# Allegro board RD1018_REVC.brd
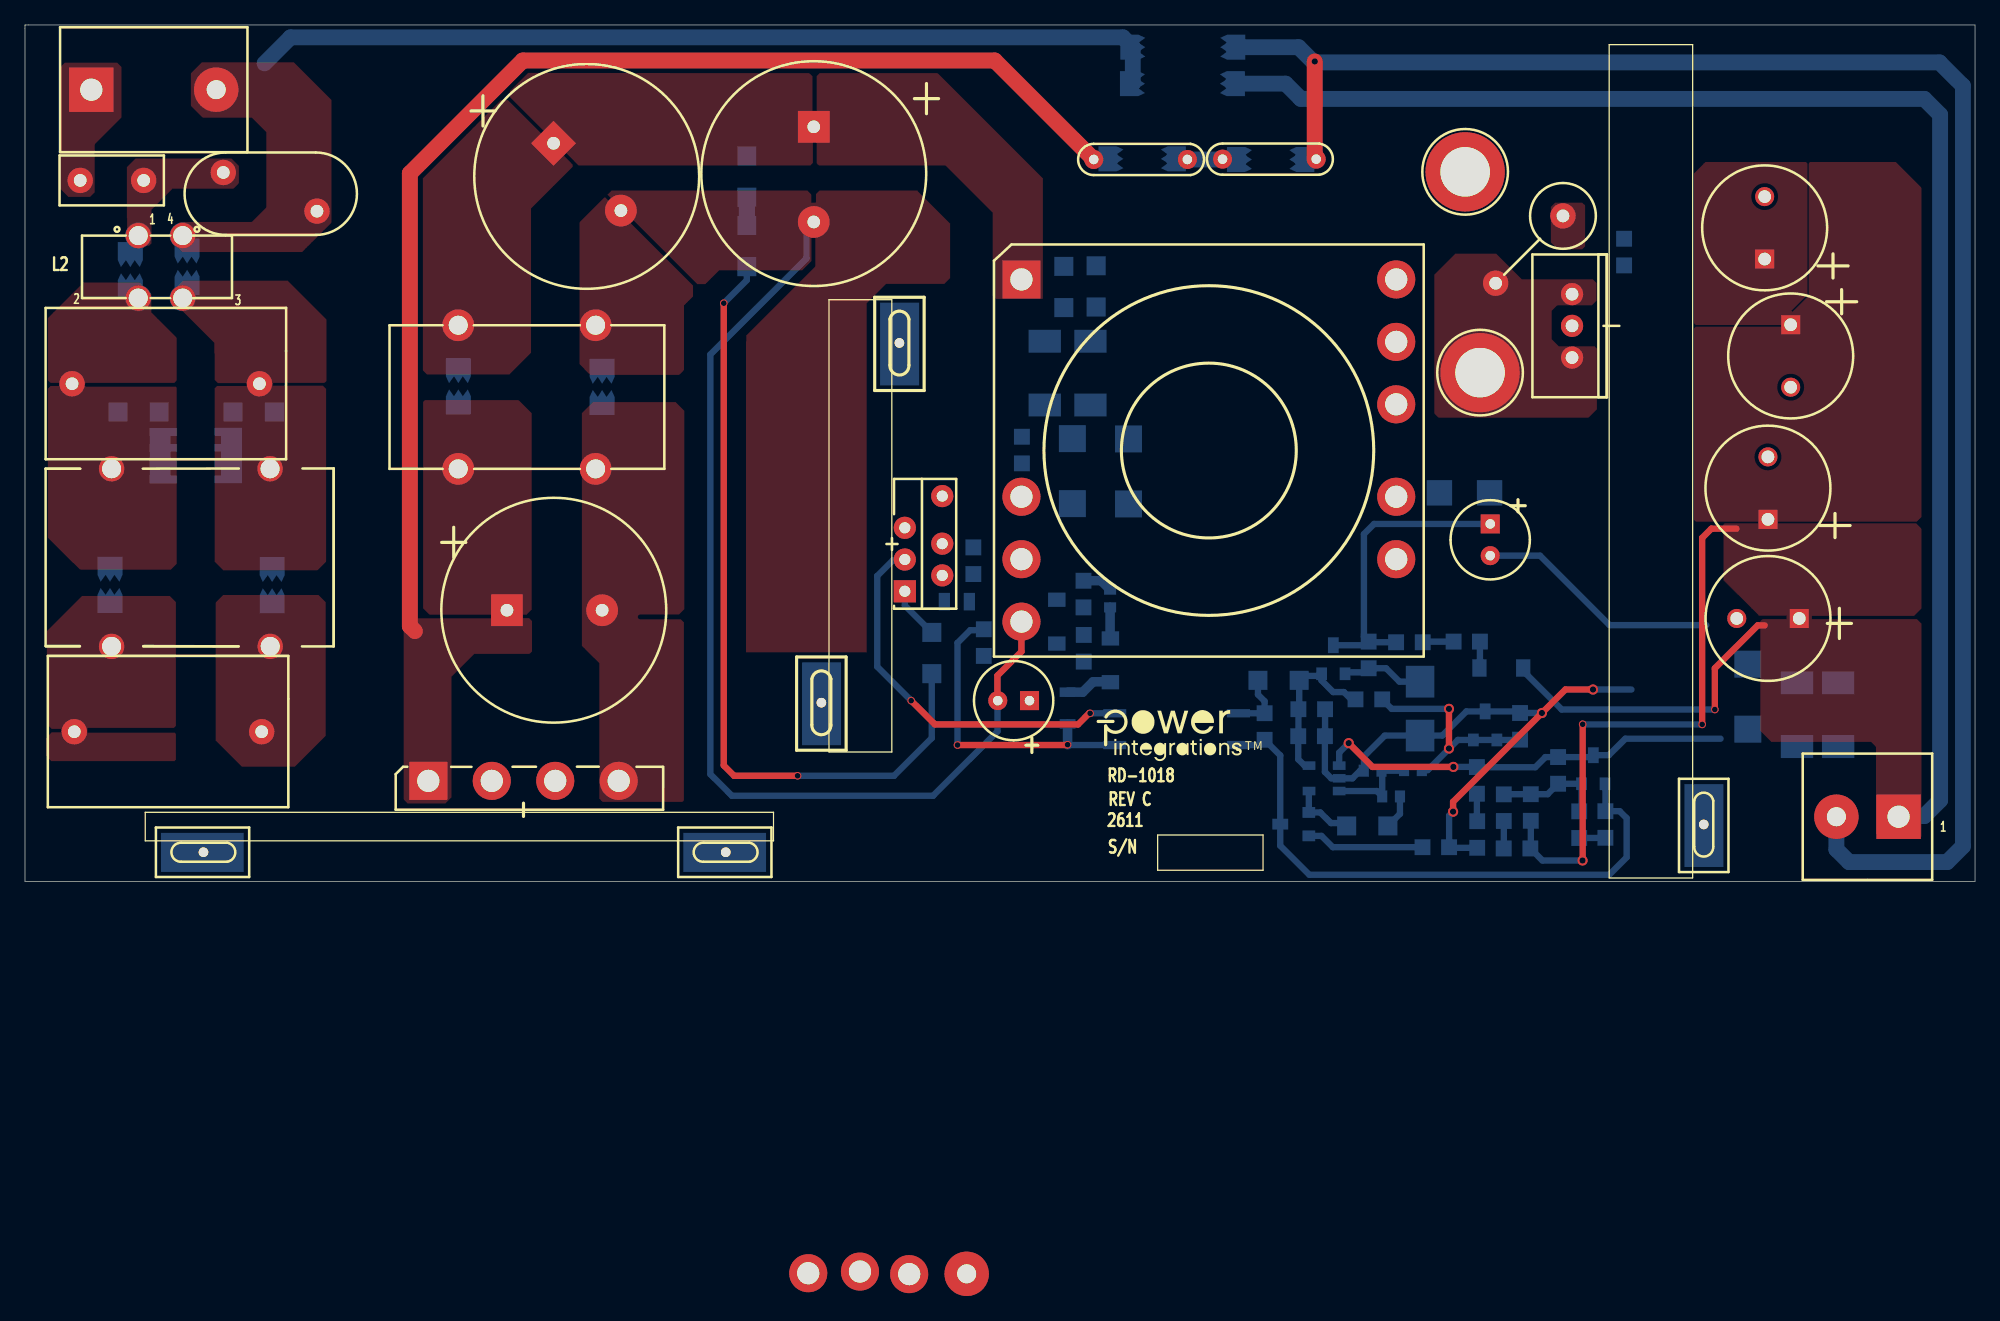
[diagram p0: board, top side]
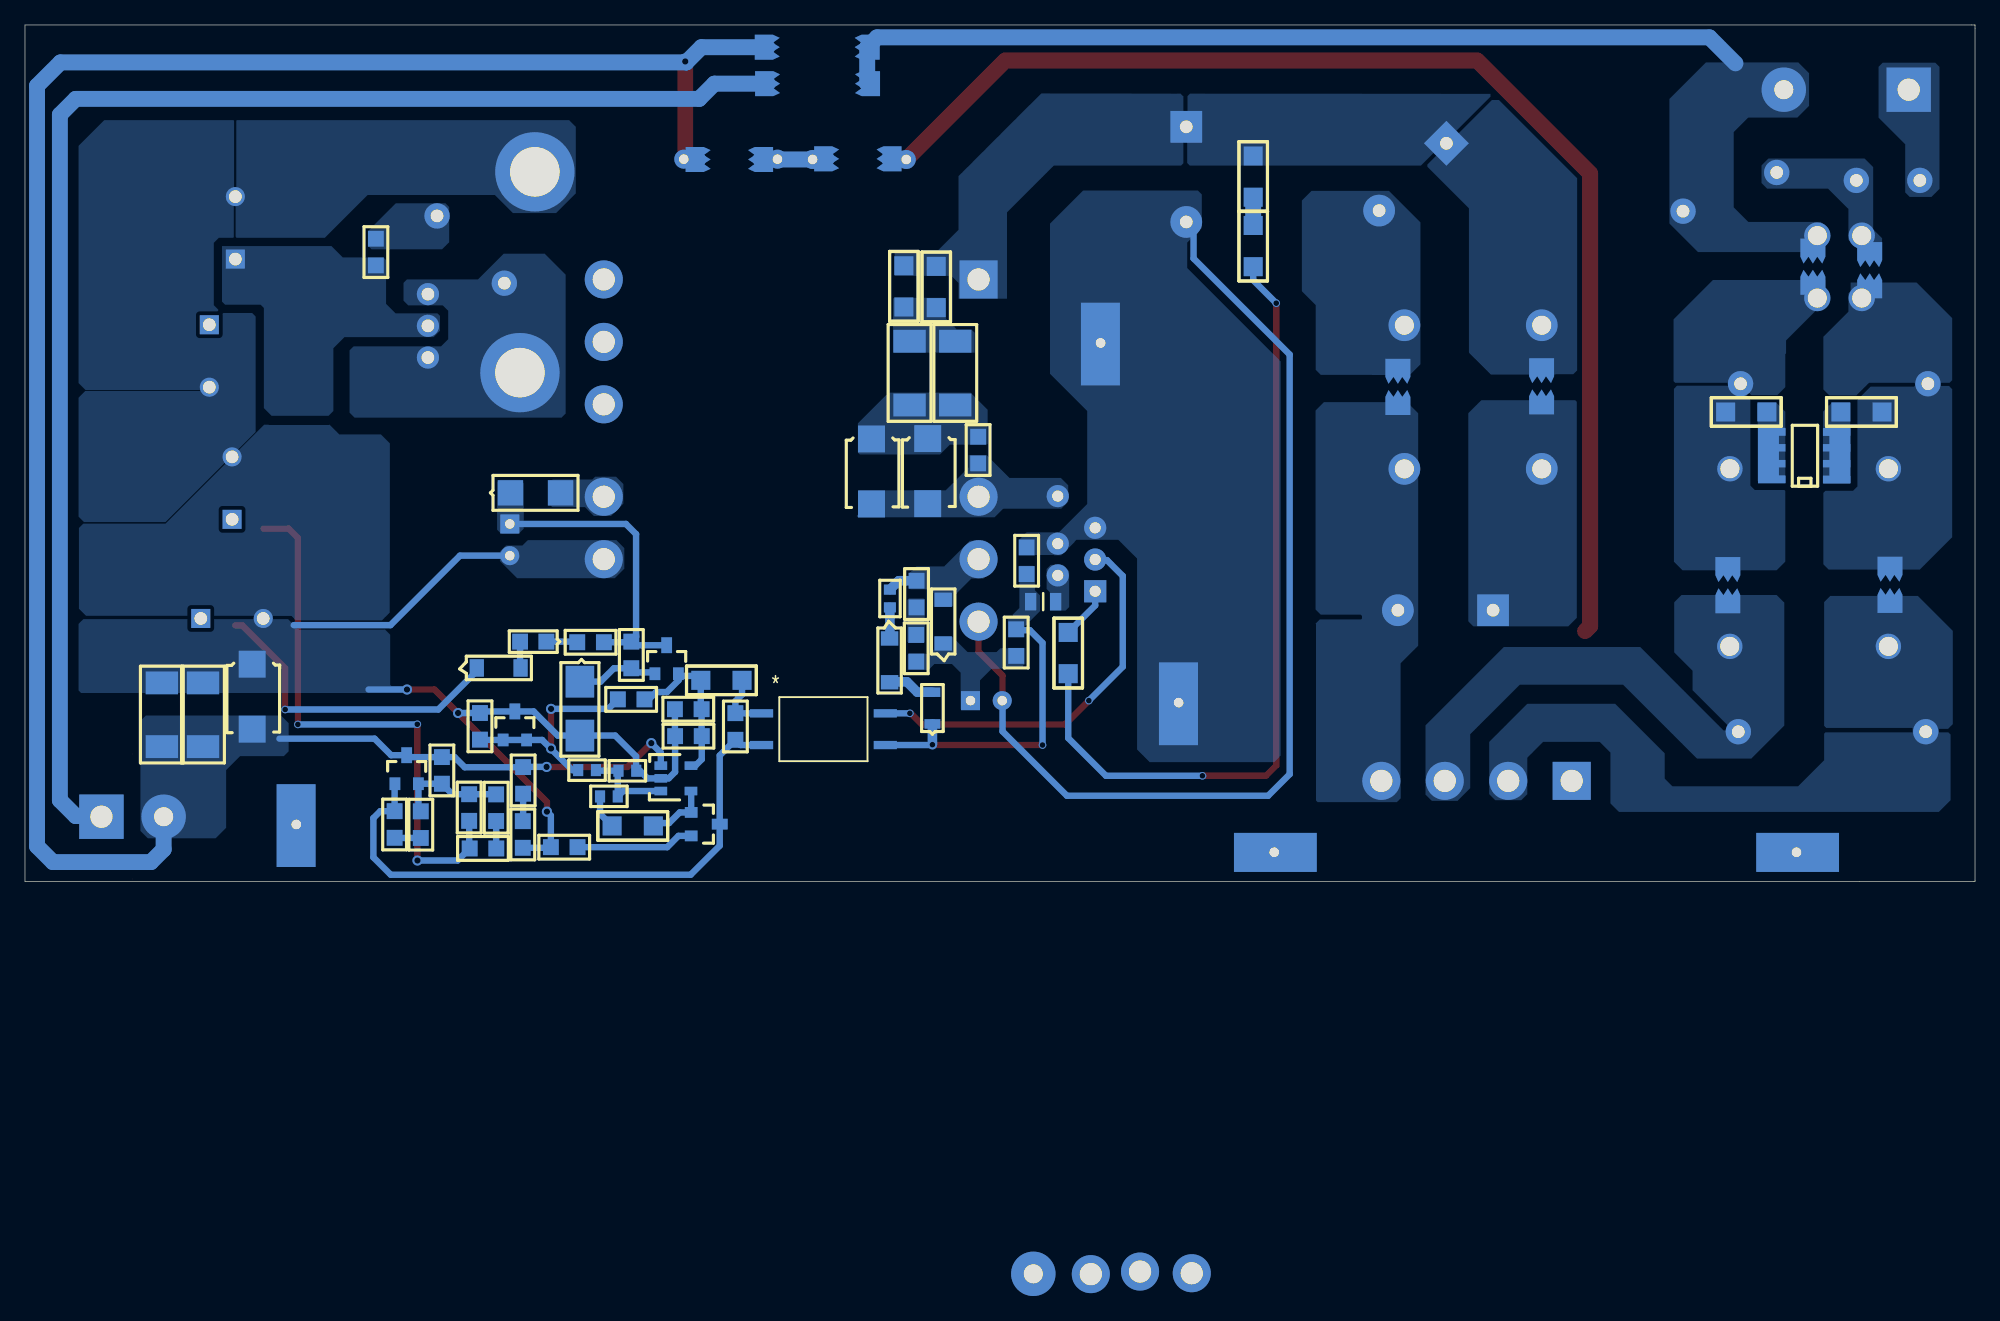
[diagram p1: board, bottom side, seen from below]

Outline 156.11 x 68.58 mm; copper layers: TOP, BOTTOM. Coordinates in mm from the lower left corner of the outline.
Outline path: 0,68.58 156.11,68.58 156.11,0 0,0 0,68.58

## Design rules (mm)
constraint set DEFAULT: min track width 0.508

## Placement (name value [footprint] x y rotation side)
BR1  GBU10KL-BP  [PIDAXBRIDGEGBU8]  32.29 8.05 0 top
C1  680 nF  [PINPXCAPRAD710X430720040]  18.95 11.99 180 top
C2  680 nF  [PINPXCAPRAD710X430720040]  18.77 39.85 180 top
C3  150 uF  [PIPOLCAPCLYD18LS7P5H37D40V]  38.58 21.72 0 top
C4  150 uF  [PIPOLCAPCLYD18LS7P5H37D40V]  42.32 59.11 315 top
C5  150 uF  [PIPOLCAPCLYD18LS7P5H37D40V]  63.14 60.43 270 top
C7  0.47 uF  [PISMC0805]  75.92 24.61 90 bottom
C8  47 pF  [PISMC0805]  79.81 35.61 270 bottom
C9  4700 pF  [PISMC1206]  83.16 49.25 270 bottom
C10  330 pF  [PISMC0805]  84.73 24.08 270 bottom
C11  22 uF  [PIPOLCAPCYLD250LS100030]  80.42 14.48 180 top
C12  100 nF  [PISMC0805]  119.68 11.35 90 bottom
C13  47 uF  [PIPOLCAPCYLD250LS100030]  117.3 28.63 270 top
C14  470 pF  [PISMC0805]  128.02 51.46 270 bottom
C15  10 nF  [PISMC0805]  116.23 7.02 90 bottom
C16  220 nF  [PISMC0603]  108.65 6.81 0 bottom
C17  220 uF  [PIPOLCAPCLYD10MM040]  141.35 44.58 270 top
C18  100 nF  [PISMC0805]  104.06 11.63 180 bottom
C19  100 nF  [PISMC0805]  101.94 13.79 0 bottom
C20  220 uF  [PIPOLCAPCLYD10MM040]  139.27 49.83 90 top
C21  220 uF  [PIPOLCAPCLYD10MM040]  139.53 28.99 90 top
C22  120 uF  [PIPOLCAPCLYD10MM040]  142.04 21.06 180 top
C23  10 nF  [PISMC0805]  126.52 5.63 270 bottom
C24  10 nF  [PISMC0805]  118.39 4.84 90 bottom
CY1  4700 pF  [PINPCAPRAD10DX7P5MM]  89.31 57.81 0 top
CY2  4700 pF  [PINPCAPRAD10DX7P5MM]  99.62 57.84 0 top
D1  BAV21WS-7-F  [PISMSOD323]  83.46 12.61 90 bottom
D2  S2M  [PISMSMB]  83.85 35.46 270 bottom
D3  S2M  [PISMSMB]  88.34 35.43 270 bottom
D4  S1MLHRVG  [PI_SM_SOD-123_12]  82.6 19.05 90 bottom
D5  US1D  [PISMDSMA]  117.25 31.11 180 bottom
D6  STTH2003CT  [PIDVTO2203]  123.85 47.16 270 top
D7  1N4148WS  [PISMDSOD323]  114.37 19.2 0 bottom
D9  S1AB-13-F  [PISMSMB]  137.92 17.4 270 bottom
F1  5 A  [PI_RST_MICROFUSE]  4.42 56.13 0 top
FL1  Hole_156mils  [PI_HOLE_156MIL]  116.48 40.74 0 top
FL2  Hole_156mils  [PI_HOLE_156MIL]  115.29 56.82 270 top
J1  CON3  [PI_HDR_3PIN_PHOENIX_196LS]  5.31 63.4 0 top
J2  CON2  [PI_HDR_2PIN_PHOENIX_196LS]  149.99 5.18 180 top
L1  10 mH  [PI_TOROID_BALUN_1]  19.63 18.82 90 top
L2  150 uH  [PI_TOROID_CMC4P_V_RDK1018]  9.07 51.71 0 top
L3  1 mH  [PI4P21P7X11P5D60]  40.18 38.79 90 top
L4  42 Ohm  [INDC2012X105N]  74.6 22.4 0 bottom
NOREF  -  []  -165.03 55.35 0 top
NOREF#2  -  []  -233.63 -242.95 0 top
NOREF#3  -  []  2.79 68.02 0 top
NOREF#4  -  []  0 68.58 0 top
NOREF#5  -  []  0 0 90 top
Q1  MMBTA06LT1  [PISMSOT23123_1]  104.75 17.73 180 bottom
Q2  MMBTA06LT1  [PISMSOT23123_1]  101.68 4.6 270 bottom
R1  100 k  [PISMR1206]  7.44 37.59 0 bottom
R2  100 k  [PISMR1206]  16.66 37.59 0 bottom
R3  2 M  [PISMR1206]  57.78 58.09 270 bottom
R4  3.30 M  [PISMR1206]  57.78 52.53 270 bottom
R5  2.20 M  [PISMR1206]  72.59 16.64 90 bottom
R6  470 k  [PISMR1206]  85.75 49.3 270 bottom
R7  20  [PISMR2010]  81.64 43.26 270 bottom
R8  20  [PISMR2010]  85.29 43.26 270 bottom
R9  3.01 k  [PISMR0805]  76.76 20.19 270 bottom
R10  47  [PISMR0603]  86.87 21.95 90 bottom
R11  100  [PISMR0805]  84.76 19.74 270 bottom
R12  4.22 k  [PISMR0805]  106.51 14.58 0 bottom
R13  53.6 k  [PISMR0603]  111.82 8.92 180 bottom
R14  20  [PI2WRESD200LS725D040]  123.12 53.29 225 top
R15  1 k  [PISMR0805]  116.26 2.69 90 bottom
R16  3.9 K  [PISMR0603]  108.6 8.86 180 bottom
R18  100  [PISMR0805]  111.9 19.15 180 bottom
R19  13 k  [PISMR0805]  107.57 17.07 90 bottom
R20  10.0 k  [PISMR1206]  109.11 4.45 180 bottom
R21  100  [PISMR0805]  114.01 2.74 180 bottom
R22  1.00 k  [PISMR0805]  99.24 13.47 270 bottom
R23  2 k  [PISMR1206]  102.01 16.1 180 bottom
R24  0.08  [PISMR2010]  145.15 15.9 270 bottom
R25  0.08  [PISMR2010]  141.86 15.9 270 bottom
R26  20.0 k  [PISMR0805]  124.42 3.48 90 bottom
R27  158 k  [PISMR0805]  120.55 4.85 90 bottom
R28  10 k  [PISMR0805]  122.73 7.82 90 bottom
R29  20 k  [PISMR0805]  120.51 2.64 180 bottom
RV1  320 Vac  [PIDISC500X225LS335X140040]  15.88 56.77 0 top
SG1  0.5mm gap  [PI_SPARK_GAP_0P5MM]  8.43 48.95 270 bottom
SG2  0.5mm gap  [PI_SPARK_GAP_0P5MM]  6.81 23.75 270 bottom
SG3  0.5mm gap  [PI_SPARK_GAP_0P5MM]  12.98 49.23 270 bottom
SG4  0.5mm gap  [PI_SPARK_GAP_0P5MM]  19.79 23.72 270 bottom
SG5  0.5mm gap  [PI_SPARK_GAP_0P5MM]  34.7 39.65 90 bottom
SG6  0.5mm gap  [PI_SPARK_GAP_0P5MM]  46.2 39.6 90 bottom
SG7  3.0mm gap  [PI_SPARK_GAP_3P0MM]  89.43 57.86 0 bottom
SG8  6.0mm gap  [PI_SPARK_GAP_6P0MM]  92.66 63.88 0 bottom
SG9  6.0mm gap  [PI_SPARK_GAP_6P0MM]  92.68 66.8 0 bottom
SG10  3.0mm gap  [PI_SPARK_GAP_3P0MM]  99.72 57.81 0 bottom
T1  PQ32/30  [PI_BBN_TDKBPQ32_30_12P]  94.77 34.5 0 top
TE1  Terminal, Eyelet, Zierick 190  [PI_ZIERICK190_EYELET]  14.29 2.34 0 top
TE2  Terminal, Eyelet, Zierick 190  [PI_ZIERICK190_EYELET]  134.39 4.56 90 top
TE3  Terminal, Eyelet, Zierick 190  [PI_ZIERICK190_EYELET]  63.75 14.32 90 top
TE4  Terminal, Eyelet, Zierick 190  [PI_ZIERICK190_EYELET]  70 43.12 90 top
TE5  Terminal, Eyelet, Zierick 190  [PI_ZIERICK190_EYELET]  56.1 2.34 0 top
U1  CAP300DG  [PI_IC_SMD_SO8_CAPZERO]  11.07 32.18 90 bottom
U2  TOP7075E  [PIICESIP76TH]  70.43 23.24 90 top
U3  SFH6106-3T  [SMD-4_VO_VIS]  92.19 12.19 180 bottom
U4  LM431BIM3/NOPB  [PISMSOT23123]  115.95 11.33 180 bottom
U5  LM321MF/NOPB  [PISMSOT235]  105.21 9.27 270 bottom
U6  LM431BIM3/NOPB  [PISMSOT23123]  124.61 7.82 180 bottom
VR1  MMSZ5243BT1G  [PI_SM_SOD-123_12]  86.89 19.46 270 bottom
VR2  SMAZ12-13-F  [PISMDO214AC12]  111.68 16 270 bottom
VR3  MMSZ5256B-7-F  [PI_SM_SOD-123_12]  119.94 17.09 180 bottom

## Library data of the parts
BR1 = DISCRETE BRIDGE_+~~-: room: 1
C1 C2 = CAP NP: alternate symbols: (pinpxcaprad710x430720040_h); room: 1
C3-C5 = CAP POL: alternate symbols: (pipolcapclyd18ls7p5H37d40H); room: 1
C7 = CAP NP: alternate symbols: (Unisem_RMCF0805UL); room: 1
C8 C10 = CAP NP: alternate symbols: (Unisem_RMCF0805UL); tolerance: 10; room: 1
C9 = CAP NP: tolerance: 10; room: 1
C11 = CAP POL: tolerance: 20; room: 1
C12 C18 C19 = CAP NP: alternate symbols: (Unisem_RMCF0805UL)
C13 = CAP POL: alternate symbols: (pipolcapcyld250ls100030h)
C14 = CAP NP: alternate symbols: (Unisem_RMCF0805UL); tolerance: 10; room: 2
C15 C23 C24 CY1 CY2 = CAP NP
C16 = CAP NP: alternate symbols: (Unisem_RMCF0603UL)
C17 C20 C21 = CAP POL: room: 2
C22 = CAP POL: alternate symbols: (pipolcapclyd395x630ls200030h); tolerance: 20; room: 2
D1 = DIODE: alternate symbols: (SOD323_UL_IPC,pismsod323_1)
D2-D4 D7 = DIODE: room: 1
D5 D9 = DIODE
D6 = D_DUAL_CK_AKA: alternate symbols: (pidvto2203vf1)
F1 = FUSE: alternate symbols: (pirstmicrofusehoz); room: 1
FL1 FL2 = FlyingLead: room: 2
J1 = CON3: alternate symbols: (pi_hdr_3pin_phoenix_196lsobl)
J2 = CON2: alternate symbols: (pi_hdr_2pin_phoenix_196lsobl)
L1 = TORRID 4P_12_43a: room: 1
L2 = TORRID 4P_12_43a
L3 = TORRID 4P_14_23: alternate symbols: (pi_toroid_CMC_RDK1018_L3)
L4 = INDUCTOR_BEAD
Q1 Q2 = NPN_BEC
R1-R8 = R: room: 1
R9 R19 R21 R22 R26-R28 = R: alternate symbols: (Unisem_RMCF0805UL)
R10 = R: alternate symbols: (Unisem_RMCF0603UL,pismr0603_1)
R11 = R: alternate symbols: (Unisem_RMCF0805UL); room: 1
R12 = R: alternate symbols: (Unisem_RMCF0805UL); room: 3
R13 R16 = R: alternate symbols: (Unisem_RMCF0603UL)
R14 = R: alternate symbols: (pi2wresd200ls900d040,pi2wvresd200ls300d040,pi2wvresd200ls400d040); room: 2
R15 R20 R23-R25 R29 = R
R18 = R: alternate symbols: (Unisem_RMCF0805UL); room: 2
RV1 = VARISTOR: alternate symbols: (pi_rad450x550ls300d040_h); room: 1
SG1-SG7 SG10 = SPARK_GAP
SG8 SG9 = SPARK_GAP: room: 1
T1 = BPQ32/30_12P/GENERIC
TE1 = TERM EYLT: room: 1
TE2-TE5 = TERM EYLT
U1 = CAPZero: room: 1
U2 = TOPSwitch-GaN_eSIP7
U3 = OPTO_A_B_AKCE: User Part Number: PN; Tolerance: TOL
U4 U6 = TL431/SOT-23_CAR
U5 = LM321_SOT23-5
VR1 VR2 = DIODE_ZENER
VR3 = DIODE_ZENER: room: 2

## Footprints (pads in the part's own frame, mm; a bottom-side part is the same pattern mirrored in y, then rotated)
INDC2012X105N
  rect 0.899x1.4 smd: 1(-1.001,0) 2(1.001,0)
PI2WRESD200LS725D040
  round 2.032 hole 1.016: 1(0,0) 2(7.62,0)
PI4P21P7X11P5D60
  round 2.54 hole 1.524: 1(-5.751,5.499) 2(-5.751,-5.499) 3(5.751,-5.499) 4(5.751,5.499)
PI_BBN_TDKBPQ32_30_12P
  rect 3.048x3.048 hole 1.778: 1(-15.001,13.701)
  round 3.048 hole 1.778: 2(-32.07,-65.875) 3(-27.93,-65.743) 4(-15.001,-3.701) 5(-15.001,-8.7) 6(-15.001,-13.701) 7(-23.988,-65.949) 8(15.001,-8.7) 9(15.001,-3.701) 10(15.001,3.701) 11(15.001,8.7) 12(15.001,13.701)
PI_HDR_2PIN_PHOENIX_196LS
  rect 3.556x3.556 hole 1.778: 1(0,0)
  round 3.556 hole 1.524: 2(4.978,0)
PI_HDR_3PIN_PHOENIX_196LS
  rect 3.556x3.556 hole 1.778: 1(0,0)
  round 3.556 hole 1.524: 2(70.079,-94.818) 3(10,0)
PI_HOLE_156MIL
  round 6.35 hole 3.962: 1(0,0)
PI_IC_SMD_SO8_CAPZERO
  rect 0.599x2.2 smd: 1(0,0) 2(1.27,0) 3(2.54,0) 4(3.81,0) 5(3.81,5.199) 6(2.54,5.199) 7(1.27,5.199) 8(0,5.199)
PI_RST_MICROFUSE
  round 2.032 hole 1.016: 1(0,0) 2(5.08,0)
PI_SM_SOD-123_12
  rect 1.143x1.397 smd: 1(0,0) 2(3.505,0)
PI_SPARK_GAP_0P5MM
  custom 0.5x0.5 smd: 1(-1.25,0) 2(1.25,0)
PI_SPARK_GAP_3P0MM
  custom 0.5x0.5 smd: 1(-2.499,0) 2(2.499,0)
PI_SPARK_GAP_6P0MM
  custom 0.5x0.5 smd: 1(-4,0) 2(4,0)
PI_TOROID_BALUN_1
  round 2.032 hole 1.524: 1(0,0) 2(14.224,0.013) 3(14.224,12.7) 4(0,12.7)
PI_TOROID_CMC4P_V_RDK1018
  round 2.032 hole 1.524: 1(0,0) 2(0,-5.001) 3(3.559,-5.001) 4(3.559,0)
PI_ZIERICK190_EYELET
  round 0.762 hole 0.762: 1(0,0)
PIDAXBRIDGEGBU8
  rect 3.048x3.048 hole 1.778: 1(0,0)
  round 3.048 hole 1.778: 2(5.08,0) 3(10.16,0) 4(15.24,0)
PIDISC500X225LS335X140040
  round 2.032 hole 1.016: 1(0,0) 2(7.501,-3.099)
PIDVTO2203
  round 1.778 hole 1.016: 1(0.127,0) 2(2.667,0) 3(5.207,0)
PIICESIP76TH
  rect 1.778x1.778 hole 0.889: 1(0,0)
  round 1.778 hole 0.889: 2(1.27,-2.997) 3(2.54,0) 4(3.81,-2.997) 5(5.08,0) 7(7.62,-2.997)
PINPCAPRAD10DX7P5MM
  round 1.524 hole 0.762: 1(-3.749,0) 2(3.749,0)
PINPXCAPRAD710X430720040
  round 2.032 hole 1.016: 1(0,0) 2(15.001,0)
PIPOLCAPCLYD10MM040
  rect 1.524x1.524 hole 1.016: 1(0,0)
  round 1.524 hole 1.016: 2(5.001,0)
PIPOLCAPCLYD18LS7P5H37D40V
  rect 2.54x2.54 hole 1.016: 1(0,0)
  round 2.54 hole 1.016: 2(7.62,0)
PIPOLCAPCYLD250LS100030
  rect 1.524x1.524 hole 0.762: 1(0,0)
  round 1.524 hole 0.762: 2(2.54,0)
PISMC0603
  rect 0.813x0.965 smd: 1(0,0) 2(1.422,0)
PISMC0805
  rect 1.27x1.27 smd: 1(0,0) 2(2.134,0)
PISMC1206
  rect 1.524x1.524 smd: 1(0,0) 2(3.302,0)
PISMDO214AC12
  rect 2.54x2.286 smd: 1(0,0) 2(4.318,0)
PISMDSMA
  rect 2.032x2.032 smd: 1(0,0) 2(4.013,0)
PISMDSOD323
  rect 1.27x1.27 smd: 1(0,0) 2(2.108,0)
PISMR0603
  rect 0.813x0.965 smd: 1(0,0) 2(1.422,0)
PISMR0805
  rect 1.27x1.27 smd: 1(0,0) 2(2.134,0)
PISMR1206
  rect 1.524x1.524 smd: 1(0,0) 2(3.302,0)
PISMR2010
  rect 1.829x2.591 smd: 1(0,0) 2(5.105,0)
PISMSMB
  rect 2.159x2.159 smd: 1(0,0) 2(5.207,0)
PISMSOD323
  rect 0.762x1.27 smd: 1(0,0) 2(2.54,0)
PISMSOT235
  rect 0.686x1.016 smd: 1(0,0) 2(1.016,0) 3(2.032,0) 4(2.032,2.413) 5(0,2.413)
PISMSOT23123
  rect 0.864x1.016 smd: 1(-1.88,0) 3(0,0)
  rect 0.864x1.27 smd: 2(-0.94,2.286)
PISMSOT23123_1
  rect 0.864x1.016 smd: 1(-0.93,-1.1) 2(0.95,-1.1)
  rect 0.864x1.27 smd: 3(0.01,1.186)
SMD-4_VO_VIS
  rect 1.854x0.66 smd: 1(-4.953,1.27) 2(-4.953,-1.27) 3(4.953,-1.27) 4(4.953,1.27)

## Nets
SGND: C12.2 C13.2 C17.2 C18.1 C19.2 C20.2 C21.2 C22.2 D9.1 FL2.1 R15.1 R16.2 R21.1 R24.1 R25.1 T1.8 U4.2 U5.2(V-) VR2.2
ISENSE: C15.2 CY2.2 D9.2 J2.2 R24.2 R25.2 R28.2 SG9.2 SG10.2 U5.1 U6.2
TOP_SOURCE: C4.2 C5.2 C7.2 C11.2 L3.3 SG6.2 T1.6 TE3.1 TE4.1 U2.4 U2.5
VBIAS: C18.2 C19.1 Q1.2(EMITTER) R12.1 R23.1 U5.5
VOUT: C14.2 C17.1 C20.1 C21.1 C22.1 D6.2(CATHODE) J2.1 R27.1 R29.1 SG8.2 VR3.1
N1180640: BR1.1 C3.1 CY1.1 L3.1 SG5.1 SG7.1
N1180998: BR1.4 C3.2 L3.2 SG6.1
N1181144: R3.2 R4.1
N1181148: C8.2 D2.2 D3.2 T1.4 U2.7
N1181266: C11.1 D4.1 R9.2 R11.2
N1181568: U2.3 U3.4(E)
N11509583: C2.2 L1.3 L2.2 R1.1 SG1.2 SG2.1
N11509663: R1.2 U1.1 U1.2 U1.3 U1.4
N11509667: R2.1 U1.5 U1.6 U1.7 U1.8(NC8)
N11509713: C2.1 L1.2 L2.3 R2.2 SG3.2 SG4.1
N11509765: F1.2 L2.1 RV1.1 SG1.1
N11509809: J1.3 L2.4 RV1.2 SG3.1 SG8.1 SG9.1
N11511065: BR1.2 C1.2 L1.4 SG2.2
N11555399: C4.1 C5.1 C9.1 L3.4 R3.1 R6.1 SG5.2 T1.1
N11558446: BR1.3(AC2) C1.1 L1.1 SG4.2
N11565135: C9.2 R6.2 R7.1 R8.1
N11566250: F1.1 J1.1
N11618494: C10.1 D4.2 R10.2 T1.5
N11648004: R4.2 R5.1
N12700328: R5.2 U2.1
N12700744: C7.1 D1.1 L4.2 R9.1 U3.3
N12704773: C10.2 R11.1
N12706416: C14.1 R14.1
N12706737: D6.1 D6.3 FL1.1 R14.2
N12714802: C13.1 D5.1 Q1.3 R18.2 R19.2
N12714870: Q1.1 R19.1 VR2.1
N12715244: R22.1 R23.2 U3.1
N12715260: C24.1 R29.2
N12715348: C23.1 Q2.3 R22.2 U3.2 U6.1
N12715398: C24.2 R26.2 R27.2 R28.1 U6.3(VREF)
N12715470: C23.2 R26.1
N12715572: C15.1 R15.2
N12715722: C12.1 R12.2 R13.1 U4.1 U4.3(VREF)
N12715816: C16.1 R13.2 R16.1 U5.3
N12715884: Q2.2(EMITTER) R21.2
N12716022: Q2.1 R20.2 U5.4
N12720334: D5.2 T1.9
N12811611: C8.1 D2.1 D3.1 R7.2 R8.2
N12855423: D1.2 VR1.2
N12855454: R10.1 VR1.1
N12858106: C16.2 R20.1
N12858350: L4.1 U2.2
N12858425: CY1.2 CY2.1 SG7.2 SG10.1
N13059333: D7.1 R18.1
N13059337: D7.2 VR3.2

Pads without a net: J1 2; T1 2 3 7 10 11 12; TE1 1; TE2 1; TE5 1

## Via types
v1: diameter 0.61, hole 0.457, TOP to BOTTOM, 9 vias
v2: diameter 0.813, hole 0.508, TOP to BOTTOM, 9 vias

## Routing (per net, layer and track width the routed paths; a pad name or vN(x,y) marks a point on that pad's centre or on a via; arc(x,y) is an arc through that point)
SGND: length 69.2
  TOP w0.508: v2(114.33,5.59) 114.33,6.38 v2(121.44,13.49) 123.32,15.37 v2(125.53,15.37)
  BOTTOM w0.508: v2(114.33,5.59) 114.01,5.27 R21.1 114.06,2.69 R15.1 ; v2(121.44,13.49) C12.2 119.56,13.61 U4.2 115.39,13.61 113.46,11.68 VR2.2 108.86,11.68 107.19,10.01 107.19,8.88 R16.2 106.88,8.86 106.27,8.26 U5.2 104.57,8.26 104.06,8.77 C18.1 104.08,11.65 C19.2 ; 117.32,26.09 121.28,26.09 126.85,20.52 134.59,20.52 ; 128.6,15.37 v2(125.53,15.37)
ISENSE: length 177.1
  TOP w0.508: v2(114.35,9.17) 107.87,9.17 v2(105.97,11.07)
  TOP w1.27: v2(103.25,65.66) 103.25,57.95 CY2.2
  BOTTOM w0.508: U5.1 105.21,10.31 v2(105.97,11.07) ; v2(114.35,9.17) 116.22,9.17 C15.2 116.24,9.14 120.9,9.14 121.72,9.96 R28.2 125.4,9.96 U6.2 126.8,10.11 128.12,11.43 135.74,11.43
  BOTTOM w1.27: CY2.2 103.34,57.81 SG10.2 ; 103.17,65.58 101.96,66.8 SG9.2 ; 103.17,65.58 v2(103.25,65.66) ; 103.17,65.58 153.26,65.58 155.14,63.7 155.14,2.82 153.87,1.55 146.02,1.55 145.01,2.57 J2.2 145.01,5.23
TOP_SOURCE: length 83.2
  TOP w0.508: T1.6 79.77,18.4 77.85,16.48 77.85,14.5 C11.2
  BOTTOM w0.508: 63.14,52.93 62.56,52.34 62.56,49.89 54.86,42.19 54.86,8.59 56.59,6.86 72.69,6.86 77.85,12.01 77.85,14.45 C11.2
VBIAS: length 13.3
  BOTTOM w0.508: U5.5 102.44,9.27 101.93,9.78 C18.2 101.94,11.65 C19.1 102.01,13.86 R23.1 102.36,16.46 103.63,16.46 103.79,16.62 ; 103.79,16.62 103.79,16.1 104.72,15.16 105.59,15.16 106.17,14.58 R12.1 ; 103.79,16.62 Q1.2
VOUT: length 187.3
  TOP w0.508: v1(124.7,12.59) 124.7,1.69 v2(124.69,1.68) ; v1(134.26,12.57) 134.26,27.51 135,28.24 137.01,28.24 ; 139.27,20.5 138.71,20.5 135.28,17.07 v1(135.28,13.77)
  BOTTOM w0.508: v2(124.69,1.68) 121.48,1.68 R29.1 120.55,2.68 R27.1 ; VR3.1 119.94,16.98 119.97,16.94 119.97,16.81 123.02,13.77 v1(135.28,13.77) ; v1(124.7,12.59) 124.71,12.57 v1(134.26,12.57)
  BOTTOM w1.27: SG8.2 100.92,63.88 102.14,62.66 152.04,62.66 153.31,61.39 153.31,6.5 152.04,5.23 150.04,5.23 J2.1
N1180640: length 100
  TOP w1.27: 31.22,20.04 30.81,20.45 30.81,56.69 39.85,65.74 77.63,65.74 CY1.1
  BOTTOM w1.27: CY1.1 85.61,57.86 SG7.1
N1181144: length 2.3
  BOTTOM w1.27: R3.2 R4.1
N1181568: length 31.3
  TOP w0.508: v1(85.27,13.46) 85.19,13.46 84.3,12.57 72.85,12.57 v1(70.94,14.48)
  BOTTOM w0.508: U3.4 v1(85.27,13.46) ; U2.3 70.39,25.73 69.49,25.73 68.22,24.46 68.22,17.2 v1(70.94,14.48)
N11509809: length 73.6
  BOTTOM w1.27: 19.18,65.51 21.26,67.59 87.9,67.59 SG9.1 88.68,63.91 SG8.1
N11618494: length 2.4
  BOTTOM w0.762: C10.1 86.16,24.08 R10.2
N11648004: length 64.1
  TOP w0.508: v1(55.94,46.3) 55.94,9.29 56.77,8.46 v1(61.85,8.46)
  BOTTOM w0.508: v1(55.94,46.3) 57.78,48.15 R4.2 ; R5.1 72.59,11.48 69.57,8.46 v1(61.85,8.46)
N12700328: length 4.2
  BOTTOM w0.508: U2.1 70.43,22.1 R5.2
N12700744: length 24.9
  TOP w0.508: v1(74.65,10.92) 83.44,10.92 v1(83.46,10.95)
  BOTTOM w0.508: v1(83.46,10.95) 83.49,10.92 U3.3 ; v1(74.65,10.92) 74.65,19.1 75.67,20.12 76.68,20.12
  BOTTOM w0.762: v1(83.46,10.95) D1.1
N12714802: length 24.4
  BOTTOM w0.508: R18.2 107.62,19.15 R19.2 ; Q1.3 107.28,18.92 R19.2 ; R19.2 107.19,19.58 107.19,27.81 108,28.63 C13.1 117.32,28.63
N12714870: length 6.6
  BOTTOM w0.508: VR2.1 110.03,16 108.96,17.07 R19.1 107.24,16.74 105.79,16.74 Q1.1
N12715244: length 5
  BOTTOM w0.508: U3.1 99.23,13.46 R22.1 99.24,14.43 98.7,14.96 R23.2
N12715260: length 2.2
  BOTTOM w0.508: R29.2 118.39,2.65 C24.1
N12715348: length 47.8
  BOTTOM w0.508: U6.1 126.52,7.8 C23.1 127.66,5.63 128.22,5.07 128.22,1.93 126.82,0.53 102.82,0.53 100.49,2.86 Q2.3 100.49,10.09 R22.2 98.82,10.92 U3.2
N12715398: length 8.9
  BOTTOM w0.508: R26.2 124.61,5.8 U6.3 R28.1 ; R28.1 121.89,6.99 R27.2 118.4,6.99 C24.2 ; R28.1 122.76,7.85
N12715470: length 2.1
  BOTTOM w0.508: R26.1 126.5,3.48 C23.2
N12715572: length 2.2
  BOTTOM w0.508: C15.1 116.23,4.85 R15.2
N12715722: length 17.7
  TOP w0.508: v2(114,13.82) v2(114,10.64)
  BOTTOM w0.508: C12.1 119.66,11.33 U4.1 U4.3 114.71,11.33 114,10.62 ; 114,10.62 v2(114,10.64) ; 114,10.62 112.29,8.92 R13.1 ; R12.2 109.41,13.82 v2(114,13.82)
N12715816: length 7.5
  BOTTOM w0.508: U5.3 108.22,7.24 C16.1 108.65,8.81 R16.1 110.35,8.86 R13.2
N12715884: length 9.5
  BOTTOM w0.508: R21.2 104.7,2.74 103.79,3.65 Q2.2
N12716022: length 5.2
  BOTTOM w0.508: R20.2 105.58,4.67 104.55,4.67 103.69,5.53 Q2.1 102.78,7.22 U5.4
N12855423: length 3.8
  BOTTOM w0.508: 86.84,15.99 86.88,15.95 VR1.2
  BOTTOM w0.762: D1.2 84.67,15.15 85.51,15.99 86.84,15.99
N12855454: length 2.5
  BOTTOM w0.508: VR1.1 86.88,19.46 86.84,19.49
  BOTTOM w0.762: R10.1 86.87,19.52 86.84,19.49
N12858106: length 2.8
  BOTTOM w0.508: C16.2 110.07,5.41 R20.1
N12858425: length 5.3
  BOTTOM w1.27: SG10.1 97.2,57.84 CY2.1 95.84,57.81 CY1.2 93,57.86 SG7.2
N13059333: length 2.5
  BOTTOM w0.508: D7.1 111.95,19.2 R18.1
N13059337: length 2.4
  BOTTOM w0.508: D7.2 116.47,16.95 116.43,16.99 VR3.2

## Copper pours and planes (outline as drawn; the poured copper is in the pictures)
SGND on BOTTOM: 108.13,25.04 108.13,26.7 108.76,27.33 115.85,27.33 116.28,26.9 117.6,26.9 118.08,26.42 118.08,25.65 116.71,24.28 108.89,24.28
SGND on BOTTOM: outline of 83 points within 112.01,15.09 151.82,60.96
ISENSE on BOTTOM: 135,10.41 135,12.67 135.61,13.28 146.43,13.28 146.86,12.85 146.86,4.04 146.28,3.45 140.84,3.45 140,4.29 140,8.92 138.89,10.03 135.38,10.03
Net_14 on BOTTOM (solid shape): 17.52,0.76 10.89,0.76 10.89,3.89 17.52,3.89
Net_15 on BOTTOM (solid shape): 59.32,0.76 52.69,0.76 52.69,3.89 59.32,3.89
Net_16 on BOTTOM (solid shape): 135.97,1.16 132.84,1.16 132.84,7.79 135.97,7.79
TOP_SOURCE on BOTTOM (solid shape): 65.33,10.91 62.2,10.91 62.2,17.54 65.33,17.54
TOP_SOURCE on BOTTOM (solid shape): 71.58,39.72 68.45,39.72 68.45,46.34 71.58,46.34
TOP_SOURCE on TOP: 63.6,55.32 71.45,55.32 71.45,55.3 74.07,52.68 74.07,48.31 73.61,47.85 68.94,47.85 67.39,46.3 67.39,18.34 57.72,18.34 57.72,43.24 57.75,43.27 57.75,43.73 63.27,49.25 63.27,51.61 63.25,51.64 62.97,51.64 62.97,49.69 62.2,48.93 55.56,48.93 54.46,47.83 53.82,47.83 48.23,53.42 48.03,53.42 47.98,53.37 47.98,53.21 53.48,47.71 53.48,46.85 52.76,46.13 52.76,40.94 52.37,40.56 45.24,40.56 44.78,41.02 44.78,41.05 44.4,41.43 44.4,52.78 46.41,54.79 46.43,54.79 47.15,54.08 47.24,54.08 47.33,54.16 47.33,54.29 46.63,54.99 46.96,55.32 62.64,55.32 62.94,55.02 62.94,54.36 63.32,54.36 63.32,55.04
TOP_SOURCE on BOTTOM: 73.34,27.95 75.92,27.95 76.5,27.37 76.5,26.14 73.74,26.14 73.71,26.11 73.15,26.11 72.09,27.18 72.09,27.2 71.93,27.36 68.58,27.36 67.08,25.86 67.08,10.57 66.07,9.55 56.11,9.55 55.59,10.07 55.59,41.64 63.07,49.12 63.07,51.16 61.9,52.32 61.9,55.02 62.2,55.32 71.4,55.32 74.05,52.67 74.05,40.65 71.07,37.67 71.07,30.23
TOP_SOURCE on BOTTOM: 53.89,47.26 52.78,46.15 52.78,40.97 52.37,40.56 48.29,40.56 48.27,40.55 46.39,40.55 46.38,40.56 45.24,40.56 44.4,41.4 44.4,52.78 46.91,55.3 53.11,55.3 53.89,54.52
VOUT on TOP: 139.09,21.01 141.02,21.01 141.02,21.29 138.81,21.29 135.97,24.13 135.97,28.57 136.07,28.68 138.73,28.68 138.73,28.8 133.76,28.8 133.6,28.96 133.6,44.27 133.62,44.26 133.62,44.28 133.76,44.42 140.59,44.42 140.59,44.55 133.76,44.55 133.6,44.7 133.6,56.69 134.52,57.61 142.57,57.61 142.7,57.48 142.7,46.99 141.41,45.71 141.5,45.62 142.8,46.91 142.8,57.51 142.9,57.61 149.76,57.61 151.82,55.55 151.82,29.18 151.43,28.8 140.31,28.8 140.31,28.68 151.38,28.68 151.82,28.24 151.82,21.84 151.24,21.27 143.05,21.27 143.05,21.01 151.46,21.01 151.82,20.65 151.82,3.61 151.64,3.43 148.64,3.43 148.18,3.89 148.18,10.77 147.78,11.18 139.8,11.18 138.91,12.06 138.91,20.83
VOUT on BOTTOM: 122.89,45.29 122.89,44.09 123.39,43.59 130.53,43.59 131.42,42.7 131.42,37.67 131.8,37.29 136.37,37.29 136.98,37.9 136.98,45.92 137.24,46.18 140.08,46.18 140.34,46.43 140.34,50.88 131.57,50.88 130.66,49.96 127.41,49.96 127.2,49.76 127.2,46.25 126.44,45.49 123.09,45.49
N1180640 on TOP: 40.56,37.49 40.56,21.77 40.16,21.36 39.4,21.36 39.34,21.31 39.34,21.13 39.4,21.08 40.36,21.08 40.59,20.85 40.59,18.41 40.4,18.22 35.98,18.22 34.15,16.4 34.15,6.74 33.64,6.24 30.65,6.24 30.31,6.57 30.31,20.66 30.72,21.07 37.63,21.07 37.72,21.16 37.72,21.31 37.67,21.36 32.38,21.36 31.88,21.87 31.88,38.4 32,38.53 39.52,38.53
N1180640 on BOTTOM: 40.56,37.49 40.56,20.83 40.16,20.42 32.56,20.42 31.88,21.11 31.88,38.4 32,38.53 39.52,38.53
N1180998 on TOP: 52.78,21.79 52.36,21.37 49.25,21.37 49.06,21.18 49.25,20.99 52.5,20.99 52.75,20.75 52.75,6.48 52.64,6.38 46.23,6.38 45.97,6.63 45.97,17.48 44.58,18.87 44.58,37.49 45.47,38.38 52.1,38.38 52.78,37.69
N1180998 on BOTTOM: 52.12,38.38 52.79,37.71 52.79,21.78 52.37,21.36 49.17,21.36 49.07,21.26 49.07,21.06 49.15,20.98 52.45,20.98 52.79,20.64 52.76,20.6 52.76,6.48 52.63,6.35 46.28,6.35 45.97,6.65 45.97,7.59 45.99,7.61 45.99,17.46 44.58,18.87 44.58,37.49 45.47,38.38
N1181148 on BOTTOM: 77.29,32.31 79.12,34.14 80.57,34.14 80.57,33.15 82.4,31.32 89.41,31.32 89.42,31.33 89.42,29.38 89.53,29.26 89.43,29.16 78.49,29.16 77.8,29.84 73.15,29.84 72.59,30.4 72.59,31.72 73.18,32.31
N1181266 on BOTTOM: 85.34,18.24 85.45,18.14 85.45,16.94 83.77,16.94 83.3,17.41 81.9,17.41 81.2,16.71 81.2,13.82 81.1,13.72 79.65,13.72 79.65,16.1 78.71,17.04 76.43,17.04 76.02,17.45 76.02,18.67 78.03,18.67 78.33,18.36 80.64,18.36 81.92,19.63 83.31,19.63 83.31,18.59 83.67,18.24
N11509583 on TOP: 10.11,45.57 12.14,43.54 12.14,40.11 11.96,39.93 4.88,39.93 4.8,39.85 4.8,39.7 4.88,39.62 12.06,39.62 12.14,39.55 12.14,25.43 11.68,24.97 4.42,24.97 3.91,25.48 3.89,25.48 1.83,27.53 1.83,39.45 2.06,39.67 2.74,39.67 2.74,39.93 2.03,39.93 1.83,40.13 1.83,45.11 4.67,47.96 9.17,47.96 10.11,47.02
N11509583 on BOTTOM: 9.41,31.64 9.77,31.28 11.98,31.28 12.14,31.11 12.14,25.4 11.71,24.97 4.42,24.97 1.83,27.56 1.83,39.42 2.08,39.67 2.74,39.67 2.77,39.7 2.77,39.93 2.03,39.93 1.83,40.13 1.83,45.11 4.67,47.96 9.96,47.96 9.96,47.27 10.13,47.09 10.13,45.62 12.14,43.61 12.14,39.4 11.66,38.91 9.5,38.91 8.48,39.93 4.88,39.93 4.8,39.85 4.8,39.7 4.88,39.62 8.36,39.62 9.41,38.57
N11509663 on BOTTOM (solid shape): 12.17,35.69 11.66,35.69 11.66,32.49 12.17,32.49 12.17,31.88 9.98,31.88 9.98,36.3 12.17,36.3
N11509663 on BOTTOM: 9.98,32 9.98,38.28 10.06,38.35 11.43,38.35 12.17,37.62 12.17,32 12.04,31.88 10.11,31.88
N11509667 on BOTTOM (solid shape): 17.37,31.9 15.19,31.9 15.19,32.51 15.7,32.51 15.7,35.71 15.19,35.71 15.19,36.32 17.37,36.32
N11509667 on BOTTOM: 15.19,31.9 17.22,31.9 17.4,32.08 17.4,38.28 17.32,38.35 15.93,38.35 15.19,37.62
N11509713 on TOP: 24.1,25.6 23.42,24.92 15.88,24.92 15.19,25.6 15.19,39.5 15.37,39.67 17.75,39.67 17.75,39.9 15.44,39.9 15.19,40.16 15.19,42.24 15.16,42.27 15.16,43.13 11.96,46.33 11.96,47.4 12.67,48.11 21.03,48.11 24.13,45.01 24.13,40.06 24,39.93 19.86,39.93 19.86,39.7 23.85,39.7 24.1,39.45
N11509713 on BOTTOM: 15.19,31.27 15.27,31.34 17.63,31.34 17.98,31.7 17.98,38.63 18.77,39.42 18.77,39.5 18.69,39.57 18.54,39.57 17.91,38.94 15.82,38.94 15.19,39.57 15.19,42.21 15.13,42.28 15.13,43.32 11.96,46.48 11.96,48.16 20.98,48.16 24.13,45.01 24.13,40.06 24,39.93 19.46,39.93 19.38,39.85 19.38,39.75 19.43,39.7 23.85,39.7 24.1,39.45 24.1,25.6 23.42,24.92 15.88,24.92 15.19,25.6
N11509765 on TOP: 10.13,51.1 9.93,50.9 8.48,50.9 8.18,51.21 8.18,53.09 8.15,53.11 8.15,57.2 8.84,57.89 16.54,57.89 17.12,57.3 17.12,55.91 16.69,55.47 11.81,55.47 10.13,53.8
N11509765 on BOTTOM: 10.13,51.38 8.71,49.96 7.57,49.96 7.44,50.09 7.44,51.51 8.15,52.22 8.15,57.2 8.84,57.89 16.54,57.89 17.09,57.33 17.09,55.93 16.64,55.47 11.76,55.47 10.13,53.85
N11509809 on TOP: 24.54,52.76 24.54,62.59 21.54,65.58 14.15,65.58 13.28,64.72 13.28,62.1 14.22,61.16 18.16,61.16 19.32,60.01 19.32,53.98 18.15,52.81 12.42,52.81 11.71,52.1 11.71,51.28 12.6,50.39 22.17,50.39
N11509809 on BOTTOM: 24.46,52.68 24.46,62.66 21.54,65.58 14.15,65.58 13.28,64.72 13.28,62.1 14.22,61.16 18.16,61.16 19.32,60.01 19.32,53.98 18.15,52.81 12.34,52.81 11.72,52.18 11.72,51.19 12.52,50.39 22.17,50.39
N11511065 on TOP: 4.57,22.86 11.58,22.86 12.08,22.36 12.08,12.45 11.93,12.29 5,12.29 5,11.91 11.98,11.91 12.08,11.81 12.08,9.74 11.96,9.63 2.11,9.63 1.7,10.03 1.7,11.51 2.13,11.94 2.9,11.94 2.9,12.22 2.13,12.22 1.75,12.6 1.75,20.04
N11511065 on BOTTOM: 4.57,22.86 11.58,22.86 12.08,22.36 12.08,12.46 11.91,12.29 5.03,12.29 5,12.27 5,11.94 11.98,11.94 12.08,11.84 12.08,9.7 13.96,7.82 14.13,7.65 14.13,7.65 14.15,7.62 24.23,7.62 24.84,8.23 24.84,10.26 28.8,14.22 35.84,14.22 38.89,11.18 38.89,6.99 38.4,6.5 36.32,6.5 35.84,6.99 35.84,9.91 34.57,11.18 30.05,11.18 29.18,10.31 29.18,6.25 28.5,5.56 2.9,5.56 1.96,6.5 1.96,11.76 2.13,11.94 2.87,11.94 2.9,11.96 2.9,12.22 2.16,12.22 1.78,12.6 1.78,20.07
N11555399 on TOP: 38.81,63.27 40.27,64.74 60.75,64.72 61.93,64.72 61.93,64.72 62.79,64.72 63.04,64.47 63.04,61.11 63.12,61.04 63.3,61.04 63.37,61.11 63.37,64.49 63.6,64.72 73.08,64.72 81.48,56.31 81.48,46.65 77.74,46.65 77.47,46.91 77.47,53.54 73.69,57.33 63.55,57.33 63.37,57.51 63.37,60.33 63.3,60.4 63.12,60.4 63.07,60.35 63.07,57.53 62.87,57.33 44.32,57.33 43.08,58.57 43.03,58.6 42.98,58.61 42.88,58.57 42.84,58.47 42.85,58.42 42.88,58.37 43.59,57.66 43.59,57.66 43.84,57.4 43.84,57.23 40.51,53.9 40.51,42.34 38.76,40.59 32.18,40.59 31.85,40.92 31.85,56.3 33.15,57.6 38.1,62.56 38.66,62.56 41.58,59.64 41.63,59.61 41.68,59.6 41.78,59.64 41.82,59.74 41.81,59.8 41.78,59.84 38.81,62.81
N11555399 on BOTTOM: 38.79,63.06 62.84,63.08 63.04,62.88 63.04,61.11 63.12,61.04 63.32,61.04 63.37,61.09 63.37,62.89 63.41,62.89 63.6,63.08 63.87,63.08 63.87,63.08 64.4,63.08 64.41,63.09 65.25,63.09 74.75,63.09 81.38,56.47 81.38,52.17 81.38,52.17 83.03,50.52 86.41,50.52 86.49,50.44 86.49,48.56 86.41,48.49 81.94,48.49 81.38,47.92 81.38,46.66 77.42,46.66 77.5,46.74 77.5,53.57 73.74,57.33 63.55,57.33 63.37,57.51 63.37,59.72 63.35,59.74 63.14,59.74 63.07,59.66 63.07,57.53 62.87,57.33 44.35,57.33 43.05,58.62 42.9,58.62 42.82,58.55 42.82,58.42 43.84,57.4 43.84,57.23 40.51,53.9 40.51,42.34 38.76,40.59 33.6,40.59 33.58,40.61 32.16,40.61 31.85,40.92 31.85,56.31 38.11,62.57 38.65,62.57 38.66,62.59 41.61,59.64 41.76,59.64 41.81,59.69 41.81,59.82 38.81,62.81 38.79,62.81
N11558446 on TOP: 17.35,9.19 15.27,11.28 15.27,22.33 15.88,22.94 23.5,22.94 24.08,22.35 24.08,11.66 21.62,9.19
N11558446 on BOTTOM: 17.91,9.83 16.68,11.07 15.27,12.48 15.27,22.33 15.88,22.94 23.5,22.94 24.08,22.35 24.08,18.34 22.61,16.87 22.61,15.31 19.8,12.5 19.8,12.22 19.93,12.09 20.13,12.09 23.15,15.11 25.13,17.09 25.13,17.1 26.8,18.77 37.72,18.77 43.99,12.5 43.99,6.96 43.48,6.45 41.43,6.45 40.41,7.47 40.41,11.79 36.45,15.75 28.17,15.75 27.05,14.63 27.05,14.63 22.25,9.83
N11565135 on BOTTOM: 86.61,42.34 80.09,42.34 80.09,43.94 80.34,44.2 81.51,44.2 82.37,45.06 82.37,46.53 82.58,46.74 86.54,46.74 86.61,46.66
N11566250 on TOP: 2.84,55.45 2.84,65.23 3.17,65.56 7.39,65.56 7.72,65.23 7.72,61.16 5.59,59.03 5.59,55.19 5.21,54.81 3.48,54.81
N11566250 on BOTTOM: 2.84,55.45 2.84,65.23 3.17,65.56 7.39,65.56 7.72,65.23 7.72,61.16 5.59,59.03 5.59,55.17 5.23,54.81 3.48,54.81
N11618494 on BOTTOM: 78.49,25.15 78.49,26.54 79.22,27.28 80.47,27.28 82.52,25.22 84.76,25.22 85.32,24.66 85.32,23.5 85.22,23.39 83.67,23.39 83.36,23.09 83.36,22.02 83.34,22 81.89,22 81.81,22.07 81.81,22.78 80.34,24.26 79.38,24.26
N12700744 on BOTTOM: 77.42,20.98 77.42,19.56 76.1,19.56 76.1,20.4 74.85,21.64 74.85,22.91 75.26,23.32 75.26,25.15 75.39,25.27 76.5,25.27 76.5,21.89
N12704773 on BOTTOM: 84.07,19.2 84.07,22.58 84.15,22.66 85.34,22.66 85.47,22.53 85.47,19.2 85.37,19.1 84.18,19.1
N12706416 on TOP: 122.15,54 122.5,54.36 124.66,54.36 124.82,54.2 124.84,54.2 124.89,54.15 124.89,50.85 124.66,50.62 122.71,50.62 122.15,51.18
N12706416 on BOTTOM: 122.15,54 122.45,54.31 126.42,54.31 128.65,52.07 128.65,50.9 128.37,50.62 122.71,50.62 122.15,51.18
N12706737 on TOP: 112.83,48.59 114.5,50.27 117.78,50.27 119.84,48.21 125.53,48.21 125.81,47.93 125.81,46.51 125.43,46.13 122.66,46.13 122.22,45.69 122.22,43.42 122.8,42.85 125.65,42.85 125.83,42.67 125.83,37.8 125.17,37.13 113.16,37.13 112.83,37.47
N12706737 on BOTTOM: 112.83,37.47 112.83,48.59 114.5,50.27 117.78,50.27 119.84,48.21 125.53,48.21 125.81,47.93 125.81,46.51 125.43,46.13 122.66,46.13 122.22,45.69 122.22,43.42 122.8,42.85 129.79,42.85 130.12,42.52 130.12,37.54 129.72,37.13 113.16,37.13
N12714802 on BOTTOM: 116.18,28.24 116.18,31.88 116.46,32.16 118.11,32.16 118.31,31.95 118.31,28.17 117.98,27.84 116.59,27.84
N12720334 on BOTTOM: 109.19,29.26 108.2,30.25 108.2,31.83 108.79,32.41 110.46,32.41 110.69,32.18 113.87,32.18 114.2,31.85 114.2,30.28 113.89,29.97 111.28,29.97 110.57,29.26
N12811611 on BOTTOM: 82.85,34.19 82.07,34.98 79.12,34.98 79.04,35.05 79.04,37.77 80.42,39.14 86.97,39.14 89.43,36.68 89.43,34.34 89.28,34.19
N12858350 on BOTTOM: 74.32,23.42 74.07,23.16 74.07,21.69 72.8,21.69 72.52,21.97 72.52,24.84 73.03,25.35 73.99,25.35 74.32,25.02

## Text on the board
Ref Des/Silkscreen Top: 2611 | RD-1018 | S/N | REV C
USER_PART_NUM_BOTTOM: 14.  FAB HOUSE LOGO,DATE CODE TO BE IN SILK SCREEN ONLY.DO NOT USE COPPER. | 13.  MATERIAL FR4 COPPER 2oz THICKNESS 0.062" | NOTES: PLEASE DELETE THESE PINS | 5 NON PLATED SLOTS
PAGE_OUTLINE: FIGURE | FINISHED_SIZE | 18.0 | 20.0 | 30.0 | 35.0 | 40.0 | 60.0 | 70.0 | 156.0 | ALL UNITS ARE IN MILS | DRILL CHART: TOP to BOTTOM | TOLERANCE_DRILL | +3.0/-3.0 | PLATED | QTY | 9 | 13 | 6 | 27 | 15 | 18 | 2 | 99 | TOTAL HOLES:
